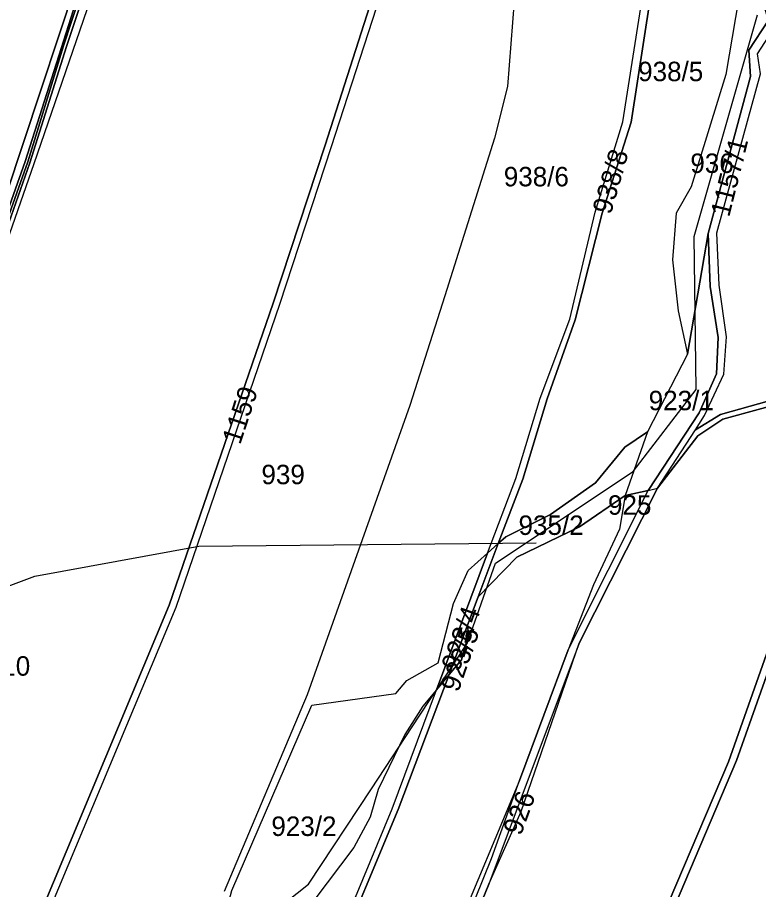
# Model space of a CAD drawing. Extents: x -623250 to -619626, y -1079612 to -1075424.
# Drawn here: x -621418.9 to -621038.1, y -1078207.1 to -1077758.8 of the extents above; entities that cross this region are included whole.
import ezdxf

# ---------------------------------------------------------------- set-up
doc = ezdxf.new("R2010")
doc.units = 0
for name, color, linetype in [('Cestní síť', 7, 'Continuous'), ('Parcela nároku', 7, 'Continuous'), ('Parcelní číslo', 7, 'Continuous'), ('Technická opateření liniová', 7, 'Continuous')]:
    doc.layers.add(name, color=color, linetype=linetype)

msp = doc.modelspace()

# ---------------------------------------------------------------- linework, layer by layer
at = {"layer": 'Cestní síť'}
for p, q in [((-621071.11, -1077871.38), (-621038.71, -1077757.43)), ((-621070.12, -1077949.96), (-621071.11, -1077871.38)), ((-621102.52, -1077992.2), (-621070.12, -1077949.96)), ((-621173.21, -1078039.35), (-621102.52, -1077992.2)), ((-621187.8, -1078080.65), (-621173.21, -1078039.35)), ((-621212.41, -1078117.96), (-621187.8, -1078080.65)), ((-621237.02, -1078155.27), (-621212.41, -1078117.96)), ((-621269.42, -1078204.38), (-621237.02, -1078155.27)), ((-621372.5, -1078285.91), (-621269.42, -1078204.38))]:
    msp.add_line(p, q, dxfattribs=at)
at = {"layer": 'Parcela nároku'}
for points in [[(-621177.33, -1078034.1), (-621162.74, -1077995.78), (-621150.37, -1077954.55), (-621135.09, -1077913.97), (-621122.12, -1077858.91), (-621107.91, -1077812.53), (-621091.44, -1077707.7), (-621074.89, -1077602.7), (-621070.92, -1077601.51), (-621087.28, -1077707.15), (-621103.56, -1077812.62), (-621118.43, -1077859.39), (-621132.39, -1077914.3), (-621146.77, -1077954.83), (-621159.27, -1077996.1), (-621171.81, -1078029.15)], [(-621287.56, -1077905.65), (-621340.92, -1078060.83), (-621413.47, -1078234.45), (-621461.2, -1078328.4), (-621462.02, -1078334.75), (-621459.02, -1078330.44), (-621410.27, -1078236.51), (-621337.32, -1078062), (-621284.16, -1077906.18), (-621257.6, -1077825.18), (-621204.75, -1077662.32), (-621198.6, -1077626.58), (-621199.7, -1077617.03), (-621206.08, -1077609.32), (-621211.44, -1077608.6), (-621204.6, -1077618.06), (-621201.95, -1077630.34), (-621208.08, -1077659.7), (-621260.76, -1077824.45)], [(-621038.22, -1077689.94), (-621054.96, -1077788.21), (-621072.71, -1077845.8), (-621080.5, -1077859.39), (-621082.28, -1077883.4), (-621079.35, -1077909.65), (-621074.64, -1077931.81), (-621064.07, -1077869.81), (-621042.31, -1077789.22), (-621043.08, -1077775.7), (-621033.05, -1077760.18), (-621036.09, -1077750.34), (-621030.49, -1077724.63), (-621029.05, -1077706.73), (-621023.14, -1077683.75), (-621018.93, -1077676.2), (-620998.71, -1077659.22), (-620993.53, -1077648.1), (-620992.91, -1077633.43), (-620988.98, -1077615.13), (-620994.15, -1077610.5), (-620992.91, -1077621.62), (-621008.82, -1077651.88), (-621032.36, -1077672.8)], [(-621364.39, -1077678.9), (-621360.94, -1077671.33), (-621356.07, -1077656.62), (-621361.81, -1077680.91), (-621375.21, -1077712.24), (-621395.2, -1077773.48), (-621413.63, -1077833.01), (-621448.87, -1077932.09), (-621484.15, -1078031.22), (-621531.47, -1078143.68), (-621559.31, -1078200.97), (-621633.61, -1078348.03), (-621651.3, -1078390.37), (-621666.67, -1078429.48), (-621674.85, -1078456.45), (-621678.32, -1078456.03), (-621652.48, -1078389.36), (-621636.77, -1078350.51), (-621560.48, -1078200.14), (-621532.5, -1078143.13), (-621485.18, -1078030.89), (-621450, -1077931.7), (-621414.98, -1077832.91), (-621377.7, -1077716.06)], [(-621536.14, -1078141.02), (-621489.42, -1078030.25), (-621424.75, -1077849.92), (-621379.95, -1077714.81), (-621377.7, -1077716.06), (-621414.98, -1077832.91), (-621450, -1077931.7), (-621485.18, -1078030.89), (-621532.5, -1078143.13), (-621560.48, -1078200.14), (-621636.77, -1078350.51), (-621652.48, -1078389.36), (-621678.32, -1078456.03), (-621682.14, -1078455.7), (-621640.24, -1078349.18), (-621601.13, -1078271)], [(-621095.09, -1077971.88), (-621106.6, -1078004.46), (-621094.8, -1078001.98), (-621068.53, -1077961.95), (-621059.69, -1077942.03), (-621058.85, -1077923.24), (-621063, -1077897.13), (-621064.07, -1077869.81), (-621074.64, -1077931.81)], [(-621090.02, -1078000.84), (-621070.42, -1077970.83), (-621057.59, -1077962.86), (-621003.37, -1077947.59), (-621003.9, -1077958.75), (-620996.31, -1077966.5), (-620996.39, -1077978.66), (-621000.18, -1077984.59), (-620998.66, -1077968.4), (-621007.24, -1077959.89), (-621007.93, -1077955.94), (-621016.43, -1077954.35), (-621056.53, -1077965.29), (-621069.21, -1077973.87)], [(-621182.13, -1078056.59), (-621171.81, -1078029.15), (-621167.94, -1078025.69), (-621145.02, -1078014.26), (-621121.95, -1077998.05), (-621106.82, -1077979.76), (-621095.09, -1077971.88), (-621106.6, -1078004.46), (-621130.13, -1078020.67), (-621162.31, -1078036.19)], [(-621122.87, -1078050.52), (-621135.92, -1078083.89), (-621094.8, -1078001.98), (-621106.6, -1078004.46), (-621109.52, -1078021.8)], [(-621203.55, -1078104.44), (-621177.33, -1078034.1), (-621171.81, -1078029.15), (-621182.13, -1078056.59), (-621187.6, -1078071.17), (-621197.06, -1078096.61)], [(-621202.73, -1078090.51), (-621194.83, -1078059.97), (-621187.33, -1078043.15), (-621177.33, -1078034.1), (-621203.55, -1078104.44), (-621210.54, -1078112.87), (-621219.88, -1078127.45), (-621233.63, -1078155.71), (-621237.73, -1078169.84), (-621246.01, -1078185.49), (-621266.68, -1078212.76), (-621275.63, -1078229.25), (-621289.76, -1078235.93), (-621307, -1078240.79), (-621324.7, -1078249.3), (-621330.24, -1078260.55), (-621336.49, -1078264.69), (-621316.51, -1078224.27), (-621310.76, -1078215.29), (-621308.79, -1078207.6), (-621267.62, -1078112.37), (-621224.49, -1078106.36), (-621218.77, -1078099.61)], [(-621197.06, -1078096.61), (-621187.6, -1078071.17), (-621187.07, -1078076.04), (-621190.71, -1078088.95)], [(-621130.31, -1078080.39), (-621176.77, -1078204.28), (-621159.99, -1078167.02)], [(-621195.01, -1078232.61), (-621206.9, -1078269.15), (-621191.82, -1078231.8), (-621175.34, -1078191.16), (-621160.87, -1078150.94)]]:
    msp.add_lwpolyline(points, close=True, dxfattribs=at)
for points in [[(-621032.36, -1077672.8), (-621038.22, -1077689.94), (-621054.96, -1077788.21), (-621072.71, -1077845.8), (-621080.5, -1077859.39), (-621082.28, -1077883.4), (-621079.35, -1077909.65), (-621074.64, -1077931.81), (-621095.09, -1077971.88), (-621106.82, -1077979.76), (-621121.95, -1077998.05), (-621145.02, -1078014.26), (-621167.94, -1078025.69), (-621171.81, -1078029.15), (-621159.27, -1077996.1), (-621146.77, -1077954.83), (-621132.39, -1077914.3), (-621118.43, -1077859.39), (-621103.56, -1077812.62), (-621087.28, -1077707.15), (-621070.92, -1077601.51), (-621064.75, -1077599.67), (-621042.92, -1077598.61), (-621016.76, -1077601.01)], [(-621595.12, -1078274.48), (-621557.95, -1078201.7), (-621530.38, -1078144.73), (-621482.76, -1078032.4), (-621447.54, -1077932.95), (-621412.5, -1077833.54), (-621393.67, -1077773.75), (-621374.06, -1077714.41), (-621361.81, -1077680.91), (-621356.07, -1077656.62), (-621352.61, -1077624.67), (-621351.52, -1077619.03), (-621346.96, -1077620.27), (-621351.15, -1077650.83), (-621352.43, -1077660.2), (-621359.74, -1077683.39), (-621370.61, -1077717.85), (-621410.49, -1077834.12), (-621445.17, -1077933.59), (-621480.01, -1078033.01), (-621527.76, -1078145.86), (-621554.92, -1078203.35), (-621592.05, -1078275.81)], [(-621410.27, -1078236.51), (-621337.32, -1078062), (-621284.16, -1077906.18), (-621257.6, -1077825.18), (-621204.75, -1077662.32), (-621198.6, -1077626.58), (-621199.7, -1077617.03), (-621176.54, -1077623.98), (-621168.66, -1077615.74), (-621161.41, -1077628.03), (-621152.23, -1077637.98), (-621149.57, -1077650.51), (-621150.79, -1077666.61), (-621158.39, -1077706.82), (-621163.73, -1077750.52), (-621167.08, -1077794.3), (-621173.84, -1077820.88), (-621199.33, -1077901.86), (-621217.33, -1077958.26), (-621270.05, -1078106.95), (-621312.71, -1078208.01)], [(-621413.47, -1078234.45), (-621340.92, -1078060.83), (-621287.56, -1077905.65), (-621260.76, -1077824.45), (-621208.08, -1077659.7), (-621214.74, -1077657.83), (-621238.69, -1077651.01), (-621258.47, -1077645.38), (-621278, -1077639.82), (-621296.82, -1077634.46), (-621331.45, -1077654.68), (-621359.74, -1077683.39), (-621370.61, -1077717.85), (-621410.49, -1077834.12), (-621445.17, -1077933.59), (-621480.01, -1078033.01), (-621527.76, -1078145.86), (-621554.92, -1078203.35), (-621592.05, -1078275.81)], [(-621095.78, -1078240.75), (-621053.62, -1078141.34), (-621012.33, -1078024.41), (-621000.18, -1077984.59), (-620996.39, -1077978.66), (-620985.35, -1077949.77), (-620963.73, -1077889.14), (-620940.04, -1077817.61), (-620928.94, -1077788.67), (-620900.05, -1077686.58), (-620895.24, -1077667.22), (-620893.94, -1077652.95), (-620900.76, -1077638.04), (-620897.89, -1077637.25), (-620890.21, -1077651.83), (-620891.22, -1077667.97), (-620895.99, -1077686.91), (-620925.3, -1077789.59), (-620936.57, -1077819.5), (-620960.78, -1077890.46), (-620985.69, -1077960.76), (-620986.94, -1077964.3), (-621049.48, -1078140.79), (-621091.98, -1078240.75)], [(-621706.68, -1078264.18), (-621667.8, -1078192.73), (-621644.39, -1078145.88), (-621611.75, -1078070.36), (-621595.29, -1078022.54), (-621583.38, -1077980.56), (-621575.53, -1077966.39), (-621533.15, -1077847.48), (-621490.7, -1077728.39), (-621473.08, -1077681.08), (-621472.16, -1077677.68), (-621473.46, -1077677.22), (-621472.37, -1077671.75), (-621379.95, -1077714.81), (-621424.75, -1077849.92), (-621489.42, -1078030.25), (-621536.14, -1078141.02), (-621601.13, -1078271)], [(-621633.61, -1078348.03), (-621559.31, -1078200.97), (-621531.47, -1078143.68), (-621484.15, -1078031.22), (-621448.87, -1077932.09), (-621413.63, -1077833.01), (-621395.2, -1077773.48), (-621375.21, -1077712.24), (-621361.81, -1077680.91), (-621374.06, -1077714.41), (-621393.67, -1077773.75), (-621412.5, -1077833.54), (-621447.54, -1077932.95), (-621482.76, -1078032.4), (-621530.38, -1078144.73), (-621557.95, -1078201.7), (-621595.12, -1078274.48)], [(-621308.79, -1078207.6), (-621267.62, -1078112.37), (-621224.49, -1078106.36), (-621218.77, -1078099.61), (-621202.73, -1078090.51), (-621194.83, -1078059.97), (-621187.33, -1078043.15), (-621177.33, -1078034.1), (-621162.74, -1077995.78), (-621150.37, -1077954.55), (-621135.09, -1077913.97), (-621122.12, -1077858.91), (-621107.91, -1077812.53), (-621091.44, -1077707.7)], [(-621163.73, -1077750.52), (-621167.08, -1077794.3), (-621173.84, -1077820.88), (-621199.33, -1077901.86), (-621217.33, -1077958.26), (-621270.05, -1078106.95), (-621312.71, -1078208.01)], [(-621033.05, -1077760.18), (-621043.08, -1077775.7), (-621042.31, -1077789.22), (-621064.07, -1077869.81), (-621063, -1077897.13), (-621058.85, -1077923.24), (-621059.69, -1077942.03), (-621068.53, -1077961.95), (-621094.8, -1078001.98), (-621090.02, -1078000.84), (-621070.42, -1077970.83), (-621065.94, -1077963.32), (-621055.87, -1077942.18), (-621054.49, -1077922.99), (-621058.29, -1077896.33), (-621059.59, -1077869.55), (-621037.01, -1077787.76), (-621038.58, -1077777.48), (-621028.9, -1077762.35)], [(-621003.37, -1077947.59), (-621057.59, -1077962.86), (-621070.42, -1077970.83), (-621065.94, -1077963.32), (-621055.87, -1077942.18), (-621054.49, -1077922.99), (-621058.29, -1077896.33), (-621059.59, -1077869.55), (-621037.01, -1077787.76), (-621038.58, -1077777.48), (-621028.9, -1077762.35)], [(-621203.04, -1078268.81), (-621176.77, -1078204.28), (-621159.99, -1078167.02), (-621130.31, -1078080.39), (-621090.02, -1078000.84), (-621069.21, -1077973.87), (-621056.53, -1077965.29), (-621016.43, -1077954.35), (-621007.93, -1077955.94), (-621007.24, -1077959.89), (-620998.66, -1077968.4), (-621000.18, -1077984.59), (-621012.33, -1078024.41), (-621053.62, -1078141.34), (-621095.78, -1078240.75)], [(-621091.98, -1078240.75), (-621049.48, -1078140.79), (-620986.94, -1077964.3), (-620921.77, -1077997.49), (-620966.72, -1078114.79), (-621011.6, -1078232.04)], [(-621191.82, -1078231.8), (-621175.34, -1078191.16), (-621160.87, -1078150.94), (-621135.92, -1078083.89), (-621094.8, -1078001.98), (-621090.02, -1078000.84), (-621130.31, -1078080.39), (-621176.77, -1078204.28), (-621203.04, -1078268.81)], [(-621257.7, -1078248.55), (-621223.28, -1078165.91), (-621197.06, -1078096.61), (-621190.71, -1078088.95), (-621187.07, -1078076.04), (-621187.6, -1078071.17), (-621182.13, -1078056.59), (-621162.31, -1078036.19), (-621130.13, -1078020.67), (-621106.6, -1078004.46), (-621109.52, -1078021.8), (-621122.87, -1078050.52), (-621135.92, -1078083.89), (-621160.87, -1078150.94), (-621195.01, -1078232.61)], [(-621260.27, -1078247.26), (-621226.36, -1078165.63), (-621203.55, -1078104.44), (-621197.06, -1078096.61), (-621223.28, -1078165.91), (-621257.7, -1078248.55)], [(-621260.27, -1078247.26), (-621226.36, -1078165.63), (-621203.55, -1078104.44), (-621210.54, -1078112.87), (-621219.88, -1078127.45), (-621233.63, -1078155.71), (-621237.73, -1078169.84), (-621246.01, -1078185.49), (-621266.68, -1078212.76)]]:
    msp.add_lwpolyline(points, dxfattribs=at)
at = {"layer": 'Technická opateření liniová'}
for p, q in [((-621409.92, -1078046.02), (-621325.76, -1078030.55)), ((-621325.76, -1078030.55), (-621152.29, -1078028.83)), ((-621769.2, -1078180.45), (-621409.92, -1078046.02))]:
    msp.add_line(p, q, dxfattribs=at)

# ---------------------------------------------------------------- texts
at = {"layer": 'Parcelní číslo'}
for s, p in [('938/5', (-621099.97, -1077791.57)), ('936', (-621073.15, -1077838.74)), ('938/6', (-621169, -1077845.63)), ('923/1', (-621094.55, -1077960.7)), ('939', (-621293.53, -1077998.73)), ('925', (-621115.46, -1078014.41)), ('935/2', (-621161.42, -1078024.79)), ('971/10', (-621453.23, -1078097.14)), ('923/2', (-621288.43, -1078179.52))]:
    msp.add_text(s, height=10, dxfattribs=at).set_placement(p)
for s, rotation, p in [('1157/1', 76.0575, (-621053.19, -1077861.79)), ('938/8', 74.0036, (-621114.03, -1077860.52)), ('1159', 71.7697, (-621304.46, -1077978.81)), ('923/4', 70.5803, (-621191.99, -1078095.41)), ('923/5', 70.7909, (-621192.37, -1078106.06)), ('926', 69.8071, (-621160.26, -1078179.82))]:
    msp.add_text(s, height=10, rotation=rotation, dxfattribs=at).set_placement(p)

doc.saveas('drawing.dxf')
